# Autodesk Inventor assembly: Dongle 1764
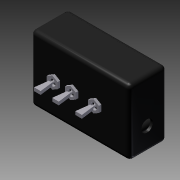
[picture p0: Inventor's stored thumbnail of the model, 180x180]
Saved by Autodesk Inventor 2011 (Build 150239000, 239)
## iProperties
Created: 2010-01
Part Number: Dongle 1764
Document SubType Name: Weldment
Designer: jgehrig
Weld Material: Welded Aluminum-6061
Author: jgehrig
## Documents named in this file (7)
- R:\CAD Archives\Electronics\Dongle\Dongle 1764.iam
- R:\CAD Archives\Electronics\Dongle\Dongle Base 1764.ipt
- R:\CAD Archives\Electronics\Dongle\DongleTop 1764.ipt
- R:\CAD Archives\Electronics\Dongle\Dongle switch 1764.ipt
- R:\CAD Archives\Electronics\Dongle\Dongle Hexagon 1764.ipt
- R:\CAD Archives\Electronics\Dongle\Dongle Flat 1764.ipt
- R:\CAD Archives\Electronics\Dongle\Dongle Blue Box 1764.ipt
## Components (20 placed, 6 different names)
1. Dongle Base 1764:1 — Mate:1, Mate:2, Angle:1, Mate:3, Mate:4, Mate:5, Mate:6, Mate:7, Mate:8, Angle:4, Mate:9, Mate:10, Mate:11, Mate:12, Mate:33, Mate:34, Mate:35
2. Dongle Blue Box 1764:1 — Mate:23, Flush:11, Flush:12, Flush:15, Mate:24, Flush:16, Mate:25, Mate:26
3. Dongle Blue Box 1764:2 — Mate:18, Flush:6, Flush:7, Mate:19, Flush:8, Flush:9, Mate:20, Mate:22
4. Dongle Blue Box 1764:3 — Mate:13, Flush:1, Flush:2, Mate:14, Flush:3, Flush:4, Mate:17, Mate:21
5. Dongle Flat 1764:1 — Flush:15, Mate:24, Flush:16
6. Dongle Flat 1764:2 — Mate:23, Flush:11, Flush:12, Flush:17
7. Dongle Flat 1764:3 — Mate:19, Flush:8, Flush:9, Flush:10
8. Dongle Flat 1764:4 — Mate:18, Flush:6, Flush:7
9. Dongle Flat 1764:5 — Mate:14, Flush:3, Flush:4, Flush:5
10. Dongle Flat 1764:6 — Mate:13, Flush:1, Flush:2
11. Dongle Hexagon 1764:1 — Mate:1, Mate:2, Angle:1, Angle:2, Mate:31, Mate:32, Angle:9
12. Dongle Hexagon 1764:2 — Mate:9, Mate:10, Angle:5, Mate:17, Flush:5, Mate:21
13. Dongle Hexagon 1764:3 — Mate:7, Mate:8, Angle:4, Angle:5, Angle:6, Mate:20, Flush:10, Mate:22
14. Dongle Hexagon 1764:4 — Mate:5, Mate:6, Angle:3, Mate:27, Mate:28, Angle:7
15. Dongle Hexagon 1764:5 — Mate:3, Mate:4, Angle:2, Angle:3, Mate:29, Mate:30, Angle:8
16. Dongle Hexagon 1764:6 — Mate:11, Mate:12, Angle:6, Mate:25, Flush:17, Mate:26
17. Dongle switch 1764:1 — Mate:31, Mate:32, Angle:9
18. Dongle switch 1764:2 — Mate:27, Mate:28, Angle:7
19. Dongle switch 1764:3 — Mate:29, Mate:30, Angle:8
20. DongleTop 1764:1 — Mate:33, Mate:34, Mate:35
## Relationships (57: Mate 33, Flush 15, Angle 9)
- Mate:1: Dongle Base 1764:1 ↔ Dongle Hexagon 1764:1
- Mate:2: Dongle Base 1764:1 ↔ Dongle Hexagon 1764:1
- Angle:1: Dongle Base 1764:1 ↔ Dongle Hexagon 1764:1
- Mate:3: Dongle Base 1764:1 ↔ Dongle Hexagon 1764:5
- Mate:4: Dongle Base 1764:1 ↔ Dongle Hexagon 1764:5
- Angle:2: Dongle Hexagon 1764:1 ↔ Dongle Hexagon 1764:5
- Mate:5: Dongle Base 1764:1 ↔ Dongle Hexagon 1764:4
- Mate:6: Dongle Base 1764:1 ↔ Dongle Hexagon 1764:4
- Angle:3: Dongle Hexagon 1764:4 ↔ Dongle Hexagon 1764:5
- Mate:7: Dongle Base 1764:1 ↔ Dongle Hexagon 1764:3
- Mate:8: Dongle Base 1764:1 ↔ Dongle Hexagon 1764:3
- Angle:4: Dongle Base 1764:1 ↔ Dongle Hexagon 1764:3
- Mate:9: Dongle Base 1764:1 ↔ Dongle Hexagon 1764:2
- Mate:10: Dongle Base 1764:1 ↔ Dongle Hexagon 1764:2
- Angle:5: Dongle Hexagon 1764:2 ↔ Dongle Hexagon 1764:3
- Mate:11: Dongle Base 1764:1 ↔ Dongle Hexagon 1764:6
- Mate:12: Dongle Base 1764:1 ↔ Dongle Hexagon 1764:6
- Angle:6: Dongle Hexagon 1764:3 ↔ Dongle Hexagon 1764:6
- Mate:13: Dongle Blue Box 1764:3 ↔ Dongle Flat 1764:6
- Flush:1: Dongle Blue Box 1764:3 ↔ Dongle Flat 1764:6
- Flush:2: Dongle Blue Box 1764:3 ↔ Dongle Flat 1764:6
- Mate:14: Dongle Blue Box 1764:3 ↔ Dongle Flat 1764:5
- Flush:3: Dongle Blue Box 1764:3 ↔ Dongle Flat 1764:5
- Flush:4: Dongle Blue Box 1764:3 ↔ Dongle Flat 1764:5
- Mate:17: Dongle Blue Box 1764:3 ↔ Dongle Hexagon 1764:2
- Flush:5: Dongle Flat 1764:5 ↔ Dongle Hexagon 1764:2
- Mate:18: Dongle Blue Box 1764:2 ↔ Dongle Flat 1764:4
- Flush:6: Dongle Blue Box 1764:2 ↔ Dongle Flat 1764:4
- Flush:7: Dongle Blue Box 1764:2 ↔ Dongle Flat 1764:4
- Mate:19: Dongle Blue Box 1764:2 ↔ Dongle Flat 1764:3
- Flush:8: Dongle Blue Box 1764:2 ↔ Dongle Flat 1764:3
- Flush:9: Dongle Blue Box 1764:2 ↔ Dongle Flat 1764:3
- Mate:20: Dongle Blue Box 1764:2 ↔ Dongle Hexagon 1764:3
- Flush:10: Dongle Flat 1764:3 ↔ Dongle Hexagon 1764:3
- Mate:21: Dongle Blue Box 1764:3 ↔ Dongle Hexagon 1764:2
- Mate:22: Dongle Blue Box 1764:2 ↔ Dongle Hexagon 1764:3
- Mate:23: Dongle Blue Box 1764:1 ↔ Dongle Flat 1764:2
- Flush:11: Dongle Blue Box 1764:1 ↔ Dongle Flat 1764:2
- Flush:12: Dongle Blue Box 1764:1 ↔ Dongle Flat 1764:2
- Flush:15: Dongle Blue Box 1764:1 ↔ Dongle Flat 1764:1
- Mate:24: Dongle Blue Box 1764:1 ↔ Dongle Flat 1764:1
- Flush:16: Dongle Blue Box 1764:1 ↔ Dongle Flat 1764:1
- Mate:25: Dongle Blue Box 1764:1 ↔ Dongle Hexagon 1764:6
- Flush:17: Dongle Flat 1764:2 ↔ Dongle Hexagon 1764:6
- Mate:26: Dongle Blue Box 1764:1 ↔ Dongle Hexagon 1764:6
- Mate:27: Dongle Hexagon 1764:4 ↔ Dongle switch 1764:2
- Mate:28: Dongle Hexagon 1764:4 ↔ Dongle switch 1764:2
- Angle:7: Dongle Hexagon 1764:4 ↔ Dongle switch 1764:2
- Mate:29: Dongle Hexagon 1764:5 ↔ Dongle switch 1764:3
- Mate:30: Dongle Hexagon 1764:5 ↔ Dongle switch 1764:3
- Angle:8: Dongle Hexagon 1764:5 ↔ Dongle switch 1764:3
- Mate:31: Dongle Hexagon 1764:1 ↔ Dongle switch 1764:1
- Mate:32: Dongle Hexagon 1764:1 ↔ Dongle switch 1764:1
- Angle:9: Dongle Hexagon 1764:1 ↔ Dongle switch 1764:1
- Mate:33: Dongle Base 1764:1 ↔ DongleTop 1764:1
- Mate:34: Dongle Base 1764:1 ↔ DongleTop 1764:1
- Mate:35: Dongle Base 1764:1 ↔ DongleTop 1764:1
